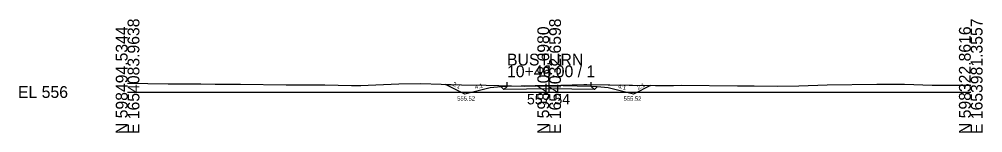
# Model space of a CAD drawing. Extents: x -26 to 1403, y -10 to 2017.
# Drawn here: x 1174.3 to 1402.8, y -9.7 to 17.3 of the extents above; entities that cross this region are included whole.
import ezdxf

# ---------------------------------------------------------------- set-up
doc = ezdxf.new("R2010")
doc.units = 0
for name, color, linetype in [('Exist Cross Section Cell', 7, 'Continuous'), ('Exist XS Center Line Elevation Label', 7, 'Continuous'), ('Exist XS Ground Line', 7, 'Continuous'), ('Prop XS Ditch Slope Text', 7, 'Continuous'), ('Prop XS Earthwork Shape', 7, 'Continuous'), ('Prop XS EOT Tick Mark', 7, 'Continuous'), ('Prop XS Finish Grade', 7, 'Continuous'), ('Prop XS Finish Grade Earthwork', 7, 'Continuous'), ('Prop XS Finish Grade Pavement', 7, 'Continuous'), ('Prop XS Pvmt Edge Slope', 7, 'Continuous'), ('Prop XS Subgrade Earthwork', 7, 'Continuous')]:
    doc.layers.add(name, color=color, linetype=linetype)

msp = doc.modelspace()

# ---------------------------------------------------------------- linework, layer by layer
at = {"layer": 'Exist Cross Section Cell'}
for p, q in [((1300, 0), (1300, 6.32)), ((1200, 0), (1300, 0)), ((1300, 0), (1400, 0))]:
    msp.add_line(p, q, dxfattribs=at)
at = {"layer": 'Exist XS Ground Line'}
for p, q in [((1200, 2.11), (1209.6, 1.93)), ((1209.6, 1.93), (1217.38, 1.93)), ((1217.38, 1.93), (1220.75, 1.86)), ((1220.75, 1.86), (1226.79, 1.89)), ((1226.79, 1.89), (1237.64, 1.71)), ((1237.64, 1.71), (1245.03, 1.73)), ((1245.03, 1.73), (1246.77, 1.7)), ((1246.77, 1.7), (1253.08, 1.58)), ((1253.08, 1.58), (1255.31, 1.53)), ((1255.31, 1.53), (1257.09, 1.62)), ((1257.09, 1.62), (1264.33, 1.93)), ((1264.33, 1.93), (1269.54, 2)), ((1269.54, 2), (1279.17, 1.71)), ((1279.17, 1.71), (1285.09, 1.67)), ((1285.09, 1.67), (1294.07, 1.36)), ((1294.07, 1.36), (1300, 1.54)), ((1300, 1.54), (1308.22, 1.78)), ((1308.22, 1.78), (1308.94, 1.79)), ((1308.94, 1.79), (1325.22, 1.53)), ((1325.22, 1.53), (1329.46, 1.55)), ((1329.46, 1.55), (1331.3, 1.6)), ((1331.3, 1.6), (1344.66, 1.45)), ((1344.66, 1.45), (1348.64, 1.45)), ((1348.64, 1.45), (1354.18, 1.41)), ((1354.18, 1.41), (1359.21, 1.47)), ((1359.21, 1.47), (1365.96, 1.69)), ((1365.96, 1.69), (1377.76, 1.87)), ((1377.76, 1.87), (1380.24, 1.89)), ((1380.24, 1.89), (1384.28, 1.86)), ((1384.28, 1.86), (1390.87, 1.63)), ((1390.87, 1.63), (1400, 1.61))]:
    msp.add_line(p, q, dxfattribs=at)
at = {"layer": 'Prop XS Earthwork Shape'}
msp.add_lwpolyline([(1310.73, 0.57), (1300, 0.79), (1289.27, 0.57), (1288.59, 1.22), (1286, 1.02), (1280, -0.48), (1275.39, 1.82), (1279.17, 1.71), (1285.09, 1.67), (1294.07, 1.36), (1300, 1.54), (1308.22, 1.78), (1308.94, 1.79), (1324.06, 1.55), (1320, -0.48), (1314, 1.02), (1311.41, 1.22)], close=True, dxfattribs=at)
at = {"layer": 'Prop XS EOT Tick Mark'}
for p, q in [((1290, 1.34), (1290, 2.34)), ((1310, 1.34), (1310, 2.34))]:
    msp.add_line(p, q, dxfattribs=at)
at = {"layer": 'Prop XS Finish Grade'}
for p, q in [((1290, 1.34), (1288.59, 1.22)), ((1311.41, 1.22), (1310, 1.34))]:
    msp.add_line(p, q, dxfattribs=at)
at = {"layer": 'Prop XS Finish Grade Earthwork'}
for p, q in [((1280, -0.48), (1275.39, 1.82)), ((1286, 1.02), (1280, -0.48)), ((1288.59, 1.22), (1286, 1.02)), ((1314, 1.02), (1311.41, 1.22)), ((1320, -0.48), (1314, 1.02)), ((1324.06, 1.55), (1320, -0.48))]:
    msp.add_line(p, q, dxfattribs=at)
at = {"layer": 'Prop XS Finish Grade Pavement'}
for p, q in [((1300, 1.54), (1290, 1.34)), ((1310, 1.34), (1300, 1.54))]:
    msp.add_line(p, q, dxfattribs=at)
at = {"layer": 'Prop XS Pvmt Edge Slope'}
for p, q in [((1289.27, 0.57), (1290, 1.34)), ((1310.73, 0.57), (1310, 1.34))]:
    msp.add_line(p, q, dxfattribs=at)
at = {"layer": 'Prop XS Subgrade Earthwork'}
for p, q in [((1288.59, 1.22), (1289.27, 0.57)), ((1300, 0.79), (1289.27, 0.57)), ((1310.73, 0.57), (1300, 0.79)), ((1311.41, 1.22), (1310.73, 0.57))]:
    msp.add_line(p, q, dxfattribs=at)

# ---------------------------------------------------------------- texts
at = {"layer": 'Exist Cross Section Cell'}
for s, p in [('E 1654083.9638', (1202.8, -10)), ('E 1654032.6598', (1302.8, -10)), ('E 1653981.3557', (1402.8, -10)), ('N 598494.5344', (1200, -10)), ('N 598408.6980', (1300, -10)), ('N 598322.8616', (1400, -10))]:
    msp.add_text(s, height=2.8, rotation=90, dxfattribs=at).set_placement(p)
for s, p in [('BUSTURN', (1290, 6.32)), ('10+46.00 / 1', (1290, 3.52)), ('EL 556', (1174, -1.4))]:
    msp.add_text(s, height=2.8, dxfattribs=at).set_placement(p)
at = {"layer": 'Exist XS Center Line Elevation Label'}
msp.add_text('557.54', height=2.5, dxfattribs=at).set_placement((1294.73, -2.94))
at = {"layer": 'Prop XS Ditch Slope Text'}
for s, rotation, p in [('2:1', 333.4349, (1276.97, 1.6)), ('4:1', 14.0362, (1282.5, 0.66)), ('4:1', 345.9638, (1316.27, 0.96)), ('2:1', 26.5651, (1321.11, 0.5))]:
    msp.add_text(s, height=1, rotation=rotation, dxfattribs=at).set_placement(p)
for p in [(1278.19, -2.03), (1317.66, -2.06)]:
    msp.add_text('555.52', height=1, dxfattribs=at).set_placement(p)

doc.saveas('drawing.dxf')
